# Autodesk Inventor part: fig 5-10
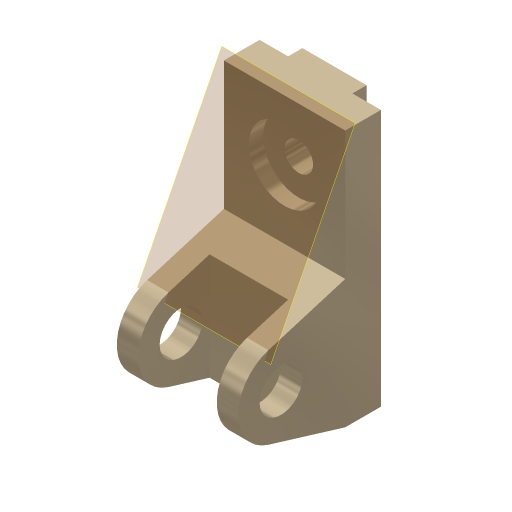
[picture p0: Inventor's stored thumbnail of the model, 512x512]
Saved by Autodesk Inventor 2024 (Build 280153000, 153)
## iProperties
Shininess: 65.0
Angle Display Precision: 2
Document Length Units: 11269
Document Angle Units: 11279
Document Time Units: 11290
Document Mass Units: 11283
Document Length Units Precision: 3
Document Angle Units Precision: 2
Compacted: False
Created: 2001-11
Part Number: fig 5-10
Document SubType Name: Modeling
Designer: Renu Muthoo
Density: 1 g/cm^3
Material: Generic
Appearance: Metal-Titanium (Polished)
Density: 0.0
Volumn: 0.0
Area: 0.0
PropertySet Name: Model Information
Control State: 0
Master: False
Checked Out: False
Author: Renu Muthoo
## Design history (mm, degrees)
sketch "Sketch2"
  geometry: L1 (33.257, 104.664)-(33.257, -75.336); L2 (33.257, -75.336)-(8.257, -75.336); L3 (8.257, -75.336)-(-45.451, -59.045); L4 (-45.451, -1.628)-(8.257, 14.664); L5 (8.257, 14.664)-(8.257, 104.664); L6 (8.257, 104.664)-(33.257, 104.664); C1 r 15 at (-36.743, -30.336); A1 r 30 centre (-36.743, -30.336) between (-45.451, -1.628) and (-45.451, -59.045)
  constraints: 12 end point, 2 centre point, 2 equal length, 2 parallel, 2 point on circle, 2 tangent, 1 coincident, 1 perpendicular, 1 vertical
  dimensions: "d0" = 180 distance of L1.start L1.end; "d1" = 30 radius of A1; "d2" = 25 distance of L5.end L1.start; "d3" = 45 distance from line of L2 A1.centre; "d4" = 70 distance from line of L1 A1.centre; "d5" = 30 diameter of C1
extrude "Extrusion1" new body sketch "Sketch2" distance "d6" = 85; taper "d7" = 0 deg
workplane "Work Plane1"
sketch "Sketch3"
  geometry: L1 (15, 62.364)-(70, 62.364); L2 (70, 62.364)-(70, -52.386); L3 (70, -52.386)-(15, -52.386); L4 (15, -52.386)-(15, 62.364); L5 (0, -45)-(0, -28.708) reference
  constraints: 8 end point, 2 parallel, 1 horizontal, 1 perpendicular
  dimensions: "d8" = 55 distance of L1.start L1.end; "d9" = 15 distance between parallel lines of L5 L4
extrude "Extrusion2" cut sketch "Sketch3" distance "d10" = 50; taper "d11" = 0 deg
sketch "Sketch4"
  geometry: L1 (0, 25)-(85, 25) reference; L2 (0, 0)-(0, 25) reference; L3 (20, 25)-(65, 25); L4 (65, 25)-(65, 35); L5 (65, 35)-(20, 35); L6 (20, 35)-(20, 25)
  constraints: 8 end point, 2 parallel, 1 horizontal, 1 perpendicular, 1 point on line
  dimensions: "d12" = 45 distance of L4.end L5.end; "d13" = 10 distance of L3.end L4.end; "d14" = 20 distance between parallel lines of L2 L6
extrude "Extrusion3" join sketch "Sketch4" stored distance "d15" = 50; taper "d16" = 0 deg
sketch "Sketch5"
  geometry: L1 (85, 0)-(85, 90) reference; L2 (0, 90)-(85, 90) reference; 1 further point
  dimensions: "d17" = 42 distance from line of L2 point (42.5, 48); "d18" = 42.5 distance from line of L1 point (42.5, 48)
hole "Hole1" sketch "Sketch5" diameter "d19" = 20; stored, may be unused: countersink angle "d23" = 82 deg, drill point angle "d25" = 118 deg; dims "d20" = 6, "d21" = 50, "d22" = 10, "d24" = 8
workplane "Work Plane4"
body "Solid1"
node "Sketch1"
